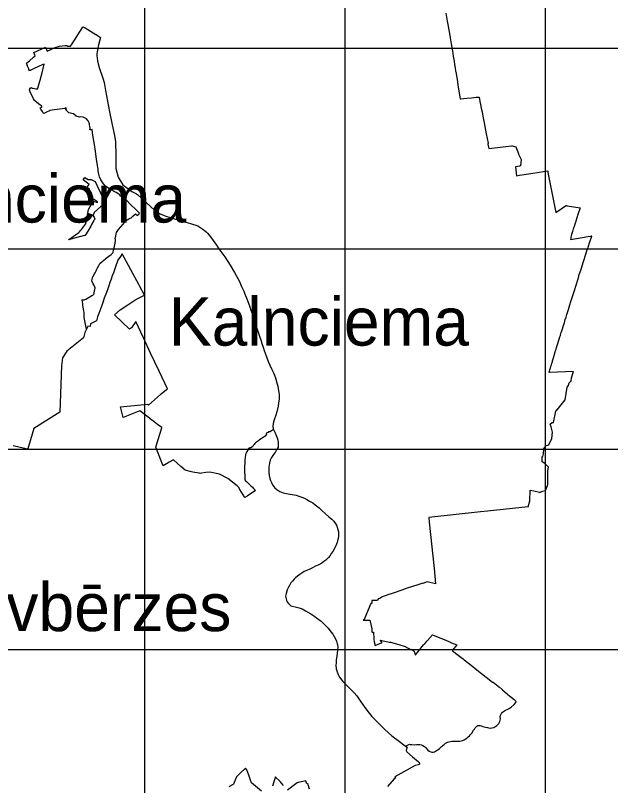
# Model space of a CAD drawing. Extents: x 459000 to 506121, y 222400 to 317452.
# Drawn here: x 471774 to 486631, y 281617 to 300827 of the extents above; entities that cross this region are included whole.
import ezdxf

# ---------------------------------------------------------------- set-up
doc = ezdxf.new("R2010")
doc.units = 0
for name, color, linetype in [('novada_robeza', 7, 'Continuous'), ('pagastu_nosaukumi', 7, 'Continuous'), ('pagastu_robezas', 7, 'Continuous'), ('Ramis', 7, 'Continuous')]:
    doc.layers.add(name, color=color, linetype=linetype)

msp = doc.modelspace()

# ---------------------------------------------------------------- linework, layer by layer
at = {"layer": 'novada_robeza'}
for points in [[(482522, 300886), (482555, 300684), (482570, 300597), (482585, 300509), (482601, 300416), (482616, 300323), (482625, 300269), (482634, 300216), (482651, 300121), (482667, 300027), (482669, 300019), (482671, 300011), (482677, 299976), (482684, 299940), (482704, 299814), (482725, 299688), (482737, 299605), (482749, 299523), (482763, 299434), (482765, 299417), (482797, 299228), (482828, 299039), (482873, 298743), (482887, 298744), (482891, 298745), (483040, 298762), (483162, 298775), (483275, 298787), (483353, 298791), (483370, 298681), (483384, 298609), (483403, 298516), (483423, 298424), (483443, 298317), (483475, 298146), (483527, 297876), (483572, 297638), (483570, 297614), (483588, 297508), (483953, 297551), (484012, 297560), (484161, 297576), (484171, 297574), (484267, 297551), (484334, 297383), (484327, 297382), (484399, 297232), (484395, 297223), (484384, 297074), (484354, 297069), (484256, 297051), (484286, 296823), (484361, 296841), (484638, 296886), (484846, 296918), (485060, 296948), (485066, 296912), (485260, 295909), (485530, 296098), (485541, 296079), (485717, 296053), (485870, 296031), (485817, 295865), (485764, 295698), (485762, 295690), (485759, 295683), (485739, 295624), (485720, 295565), (485714, 295548), (485708, 295532), (485703, 295516), (485699, 295500), (485688, 295467), (485677, 295435), (485658, 295364), (485638, 295294), (485635, 295267), (485632, 295239), (485777, 295263), (485921, 295287), (485967, 295294), (486012, 295302), (486065, 295310), (486117, 295318), (486138, 295322), (486159, 295326)], [(484571, 288568), (484571, 288572), (484614, 288720), (484620, 288986), (484716, 288971), (484852, 288933), (484861, 288930), (484862, 288930), (484930, 288957), (485006, 288979), (485057, 289098), (485060, 289123), (485066, 289343), (485068, 289447), (485065, 289469), (485079, 289558), (485070, 289568), (485067, 289571), (485058, 289580), (484999, 289645), (484936, 289684), (484924, 289690), (484925, 289825), (484942, 289822), (484952, 289892), (484964, 290017), (485023, 290101), (485092, 290119), (485168, 290270), (485181, 290430), (485146, 290567), (485123, 290634), (485175, 290677), (485182, 290677), (485199, 290671), (485205, 290674), (485267, 290958), (485271, 290961), (485285, 290990), (485296, 290991), (485496, 291242), (485544, 291554), (485581, 291592), (485581, 291608), (485593, 291664), (485640, 291702), (485646, 291705), (485656, 291786), (485702, 291942), (485703, 291946), (485102, 291920), (485094, 291921), (485099, 291938), (485104, 291955), (485112, 291983), (485120, 292010), (485127, 292029), (485133, 292048), (485137, 292062), (485141, 292076), (485152, 292113), (485163, 292150), (485171, 292172), (485178, 292194), (485181, 292203), (485183, 292213), (485207, 292290), (485230, 292367), (485232, 292376), (485233, 292384), (485235, 292390), (485237, 292397), (485240, 292402), (485242, 292407), (485241, 292408), (485239, 292408), (485242, 292416), (485245, 292424), (485258, 292465), (485270, 292505), (485284, 292547), (485297, 292590), (485314, 292644), (485332, 292698), (485348, 292753), (485365, 292807), (485372, 292826), (485378, 292845), (485384, 292864), (485390, 292882), (485401, 292919), (485412, 292956), (485431, 293013), (485449, 293070), (485463, 293114), (485476, 293158), (485500, 293239), (485520, 293304), (485540, 293369), (485577, 293489), (485614, 293609), (485639, 293688), (485664, 293767), (485687, 293840), (485710, 293912), (485727, 293967), (485769, 294101), (485811, 294235), (485836, 294317), (485839, 294327), (485842, 294337), (485895, 294501), (485954, 294686), (486014, 294871), (486032, 294929), (486050, 294987), (486051, 294990), (486051, 294992), (486106, 295155), (486160, 295318), (486158, 295318), (486157, 295319), (486158, 295322), (486159, 295326)], [(484571, 288568), (483555, 288459), (483386, 288441), (482092, 288302), (482104, 288190), (482227, 287030), (482264, 286652), (482264, 286649), (482052, 286698), (481943, 286661), (481941, 286662), (481820, 286624), (481556, 286537), (481424, 286492), (481203, 286418), (481067, 286373), (481004, 286352), (481005, 286346), (480932, 286321), (480887, 286289), (480837, 286277), (480832, 286279), (480814, 286234), (480671, 286233), (480675, 286164), (480648, 286162), (480624, 286103), (480480, 285762), (480457, 285742), (480466, 285742), (480496, 285742), (480526, 285743), (480564, 285743), (480566, 285743), (480620, 285743), (480667, 285529), (480669, 285507), (480672, 285481), (480674, 285455), (480676, 285440), (480687, 285440), (480714, 285442), (480722, 285278), (480723, 285268), (480731, 285204), (480757, 285114), (480926, 285187), (480875, 285244), (480917, 285238), (481104, 285197), (481145, 285194), (481192, 285181), (481345, 285134), (481507, 285082), (481561, 285053), (481705, 284988), (481715, 284982), (481724, 284973), (481741, 284899), (481754, 284873), (481760, 284876), (481768, 284886), (481836, 284971), (481960, 285125), (481987, 285155), (481991, 285151), (482046, 285218), (482057, 285232), (482182, 285379), (482408, 285286), (482519, 285240), (482608, 285203), (482661, 285180), (482793, 285126), (482792, 285125), (482685, 284994), (482685, 284980), (482687, 284979), (482826, 284871), (482891, 284820), (482949, 284775), (482976, 284754), (483194, 284586), (483254, 284538), (483683, 284194), (483696, 284198), (483825, 284095), (483834, 284077), (483848, 284077), (483928, 284014), (483932, 284004), (484001, 283951), (483993, 283947), (484030, 283918), (484049, 283903), (484053, 283900), (484098, 283866), (484151, 283823), (484220, 283763), (484260, 283728), (484266, 283723), (484275, 283712)], [(483420, 283101), (483442, 283093), (483505, 283072), (483559, 283063), (483584, 283059), (483634, 283053), (483665, 283054), (483720, 283066), (483744, 283081), (483769, 283095), (483791, 283113), (483814, 283137), (483838, 283163), (483858, 283198), (483865, 283216), (483879, 283283), (483878, 283344), (483884, 283366), (483889, 283385), (483906, 283413), (483930, 283445), (483955, 283465), (484009, 283496), (484048, 283516), (484083, 283533), (484106, 283548), (484145, 283577), (484220, 283637), (484262, 283690), (484275, 283712)], [(481511, 282597), (481614, 282646), (481629, 282644), (481667, 282640), (481724, 282637), (481783, 282642), (481827, 282645), (481872, 282639), (481908, 282631), (481945, 282614), (481982, 282591), (482011, 282564), (482067, 282503), (482102, 282477), (482141, 282459), (482171, 282453), (482204, 282454), (482235, 282461), (482263, 282472), (482288, 282488), (482315, 282507), (482353, 282533), (482380, 282560), (482403, 282580), (482428, 282602), (482448, 282621), (482477, 282645), (482511, 282676), (482559, 282703), (482590, 282712), (482632, 282719), (482670, 282721), (482702, 282724), (482749, 282723), (482799, 282724), (482807, 282723), (482831, 282722), (482840, 282722), (482863, 282724), (482897, 282730), (482946, 282740), (482977, 282754), (483004, 282771), (483040, 282800), (483078, 282833), (483108, 282861), (483129, 282884), (483164, 282925), (483211, 282997), (483230, 283027), (483253, 283056), (483271, 283077), (483294, 283098), (483317, 283113), (483345, 283116), (483375, 283113), (483409, 283105), (483420, 283101)], [(481511, 282597), (481551, 282578), (481547, 282552), (481540, 282530), (481534, 282515), (481531, 282506), (481528, 282496), (481529, 282488), (481535, 282475), (481544, 282461), (481688, 282338), (481828, 282217), (481851, 282192), (481856, 282186), (481859, 282177), (481860, 282156), (481860, 282155), (481827, 282131), (481750, 282122), (481469, 281962), (481247, 281835), (481274, 281814), (481231, 281787), (481066, 281595)], [(477920, 281477), (477666, 281688), (477654, 281731), (477603, 281875), (477553, 282012), (477514, 282049), (477490, 282026), (477410, 281949), (477294, 281838), (477249, 281733), (477215, 281652), (477211, 281644), (477102, 281583)], [(478465, 281616), (478382, 281715), (478364, 281734), (478355, 281743), (478276, 281822), (478263, 281835), (478224, 281714), (478188, 281600)], [(479116, 281531), (479085, 281637), (479081, 281645), (479042, 281679), (479024, 281736), (478844, 281698), (478822, 281693), (478805, 281685), (478771, 281660), (478564, 281501)]]:
    msp.add_lwpolyline(points, dxfattribs=at)
at = {"layer": 'pagastu_robezas'}
for points in [[(473547, 292998), (473495, 293293), (473494, 293330), (473491, 293410), (473490, 293419), (473486, 293446), (473477, 293510), (473461, 293592), (473455, 293647), (473448, 293683), (473441, 293739), (473464, 293731), (473492, 293733), (473507, 293741), (473529, 293752), (473613, 293797), (473686, 293839), (473709, 293851), (473724, 293869), (473729, 293875), (473735, 293883), (473738, 293887), (473742, 293907), (473756, 293990), (473762, 294028), (473739, 294087), (473719, 294128), (473718, 294130), (473680, 294204), (473687, 294242), (473702, 294290), (473711, 294308), (473751, 294381), (473764, 294409), (473789, 294455), (473800, 294477), (473811, 294500), (473826, 294531), (473858, 294590), (473865, 294606), (473880, 294637), (473929, 294682), (473930, 294683), (473938, 294689), (474024, 294757), (474041, 294771), (474109, 294821), (474161, 294865), (474162, 294865), (474190, 294887), (474203, 294902), (474211, 294919), (474223, 294968), (474229, 294996), (474262, 295143), (474263, 295149), (474272, 295205), (474273, 295211), (474272, 295240), (474272, 295240), (474262, 295259), (474274, 295298), (474284, 295324), (474293, 295383), (474299, 295415), (474314, 295441), (474352, 295491), (474463, 295617), (474493, 295654), (474556, 295722), (474563, 295725), (474605, 295751), (474639, 295769), (474665, 295776), (474707, 295818), (474770, 295880), (474813, 295833), (474860, 295879), (474863, 295882), (474876, 295895), (474876, 295895), (474757, 296011), (474673, 296089), (474522, 296240), (474476, 296273), (474382, 296325), (474385, 296329), (474393, 296345), (474370, 296357), (474355, 296367), (474355, 296367), (474355, 296368), (474287, 296408), (474146, 296485), (474081, 296530), (474027, 296572), (473976, 296623), (473939, 296677), (473908, 296729), (473877, 296803), (473859, 296865), (473851, 296908), (473844, 296952), (473837, 296991), (473830, 297037), (473824, 297087), (473800, 297243), (473793, 297302), (473775, 297437), (473745, 297608), (473707, 297839), (473697, 297904), (473688, 297980), (473661, 297976), (473640, 297974), (473636, 297974), (473641, 298012), (473634, 298057), (473627, 298102), (473624, 298119), (473617, 298150), (473594, 298196), (473547, 298244), (473498, 298276), (473462, 298289), (473409, 298297), (473376, 298287), (473293, 298314), (473223, 298371), (473110, 298395), (473029, 298478), (473050, 298499), (473032, 298521), (473012, 298505), (472627, 298457), (472625, 298448), (472550, 298412), (472481, 298378), (472477, 298377), (472447, 298430), (472410, 298491), (472400, 298505), (472388, 298519), (472392, 298521), (472441, 298546), (472423, 298570), (472403, 298587), (472363, 298617), (472293, 298670), (472255, 298705), (472225, 298749), (472133, 298938), (472131, 298958), (472121, 298971), (472124, 298977), (472160, 299030), (472190, 299016), (472219, 299010), (472249, 299002), (472253, 299002), (472283, 298996), (472290, 298996), (472311, 298995), (472335, 298998), (472337, 298998), (472333, 299009), (472384, 299185), (472392, 299214), (472430, 299333), (472441, 299398), (472494, 299607), (472459, 299601), (472350, 299556), (472226, 299497), (472142, 299456), (472129, 299451), (472112, 299481), (472107, 299493), (472100, 299512), (472092, 299531), (472086, 299545), (472080, 299561), (472056, 299621), (472051, 299635), (472096, 299673), (472125, 299698), (472230, 299785), (472265, 299816), (472238, 299898), (472526, 300038), (472569, 299937), (472770, 300027), (472875, 300058), (473010, 300075), (473056, 300073), (473085, 300061), (473151, 300061), (473171, 300094), (473246, 300213), (473387, 300431), (473396, 300445), (473461, 300545), (473512, 300515), (473783, 300354), (473791, 300350), (473796, 300347), (473800, 300345), (473899, 300279), (473850, 300089), (473813, 299921), (473806, 299869), (473804, 299824), (473824, 299692), (473841, 299622), (473866, 299531), (473968, 299236), (473990, 299151), (474020, 298955), (474122, 298424), (474191, 298099), (474247, 297833), (474271, 297675), (474278, 297333), (474282, 297050), (474283, 297012), (474336, 296796), (474460, 296604), (474460, 296603), (474578, 296508), (474677, 296437), (474801, 296378), (474824, 296362), (475248, 295971), (475391, 295878), (475526, 295818), (475639, 295783), (475858, 295724), (476149, 295635), (476324, 295580), (476357, 295566), (476451, 295497), (476534, 295429), (476567, 295399), (476620, 295334), (476713, 295215), (476790, 295098), (476855, 295001), (476998, 294802), (477138, 294594), (477244, 294417), (477367, 294189), (477422, 294063), (477473, 293952), (477493, 293902), (477552, 293756), (477625, 293561), (477655, 293474), (477685, 293388), (477706, 293322), (477727, 293255), (477778, 293104), (477803, 293030), (477835, 292928), (477866, 292827), (477897, 292734), (477927, 292641), (477956, 292554), (477985, 292467), (478007, 292401), (478030, 292335), (478081, 292197), (478122, 292106), (478177, 291997), (478225, 291893), (478270, 291785), (478311, 291630), (478325, 291576), (478350, 291416), (478355, 291379), (478358, 291350), (478358, 291329), (478355, 291264), (478344, 291159), (478333, 291083), (478304, 290943), (478275, 290856), (478230, 290741), (478208, 290649), (478200, 290572), (478209, 290516), (478217, 290499)], [(474041, 296262), (474038, 296258), (473951, 296101), (473936, 296080), (473903, 296057), (473743, 295913), (473717, 295839), (473708, 295842), (473710, 295836), (473742, 295791), (473759, 295757), (473756, 295748), (473744, 295726), (473733, 295708), (473678, 295612), (473657, 295571), (473585, 295449), (473528, 295356), (473514, 295332), (473514, 295332), (473499, 295336), (473405, 295311), (473398, 295309), (473097, 295228), (473109, 295238), (473357, 295410), (473377, 295429), (473395, 295452), (473422, 295484), (473523, 295616), (473559, 295743), (473601, 295985), (473712, 296193), (473823, 296159), (473825, 296159), (473824, 296179), (473690, 296257), (473649, 296278), (473646, 296280), (473627, 296503), (473561, 296534), (473569, 296546), (473617, 296613), (473464, 296723), (473507, 296787), (473588, 296733), (473664, 296737), (473762, 296683), (473816, 296579), (473831, 296535), (473870, 296457), (473927, 296343), (473950, 296305), (473962, 296290), (473971, 296285), (474023, 296264), (474055, 296324), (474115, 296438), (474116, 296440), (474126, 296469), (474148, 296455), (474041, 296262)], [(478217, 290499), (478146, 290449), (478136, 290442), (478129, 290437), (478121, 290443), (478108, 290444), (478096, 290438), (478084, 290427), (478071, 290412), (478064, 290431), (478033, 290398), (478046, 290382), (478007, 290336), (477956, 290302), (477893, 290255), (477860, 290231), (477844, 290220), (477815, 290198), (477804, 290189), (477790, 290180), (477771, 290162), (477754, 290147), (477735, 290126), (477713, 290097), (477700, 290078), (477672, 290055), (477666, 290050), (477645, 290034), (477639, 290041), (477637, 290040), (477627, 290038), (477620, 290036), (477607, 290030), (477593, 290022), (477582, 290000), (477581, 289999), (477545, 289937), (477525, 289900), (477517, 289866), (477508, 289801), (477500, 289737), (477505, 289736), (477505, 289733), (477500, 289669), (477499, 289647), (477493, 289590), (477493, 289567), (477492, 289519), (477496, 289439), (477497, 289399), (477499, 289386), (477499, 289361), (477500, 289336), (477501, 289293), (477503, 289241), (477503, 289241), (477521, 289220), (477544, 289199), (477643, 289103), (477661, 289085), (477681, 289066), (477719, 289028), (477753, 288997), (477770, 288981), (477758, 288972), (477568, 288846), (477558, 288839), (477501, 288802), (477501, 288801), (477373, 289001), (477367, 289014), (477367, 289020), (477369, 289025), (477372, 289028), (477363, 289038), (477356, 289045), (477353, 289049), (477313, 289094), (477075, 289276), (476870, 289385), (476630, 289432), (476627, 289432), (476525, 289422), (476417, 289410), (476389, 289405), (476365, 289407), (476205, 289438), (476140, 289451), (476008, 289483), (475907, 289573), (475724, 289746), (475611, 289682), (475561, 289650), (475550, 289643), (475461, 289593), (475456, 289607), (475281, 290059), (475341, 290252), (475430, 290538), (475432, 290545), (475325, 290626), (475198, 290723), (475182, 290735), (475129, 290775), (475118, 290783), (475086, 290808), (474881, 290967), (474468, 290799), (474401, 291068), (474825, 291103), (475077, 291127), (475099, 291108), (475397, 291374), (475415, 291390), (475550, 291497), (475569, 291512), (475361, 291954), (475148, 292404), (474968, 292784), (474778, 293191), (474672, 293032), (474626, 293004), (474244, 293359), (474386, 293481), (474581, 293611), (474780, 293739), (474995, 293851), (474870, 294086), (474855, 294114), (474707, 294390), (474443, 294880), (474399, 294817), (474335, 294721), (474282, 294579), (474248, 294484), (474219, 294406), (474193, 294328), (474164, 294252), (474134, 294165), (474106, 294085), (474079, 294011), (474045, 293917), (473993, 293771), (473955, 293665), (473930, 293593), (473909, 293528), (473880, 293455), (473856, 293392), (473827, 293307), (473795, 293209), (473646, 293131), (473644, 293069), (473581, 293075), (473579, 293070), (473549, 292998), (473547, 292998)], [(473547, 292998), (473506, 292921), (473475, 292782), (473055, 292456), (472948, 292286), (472929, 292089), (472884, 290930), (472238, 290525), (472089, 290015), (472090, 290010), (472085, 290010), (471896, 290051), (471715, 290090)], [(478217, 290499), (478256, 290415), (478284, 290351), (478307, 290291), (478323, 290229), (478336, 290171), (478337, 290114), (478331, 290057), (478294, 289990), (478266, 289941), (478215, 289878), (478165, 289800), (478137, 289730), (478117, 289658), (478104, 289563), (478104, 289490), (478103, 289428), (478111, 289349), (478127, 289273), (478142, 289225), (478165, 289176), (478193, 289121), (478245, 289050), (478299, 289002), (478371, 288951), (478461, 288918), (478585, 288892), (478779, 288857), (478852, 288834), (478926, 288807), (478994, 288782), (479050, 288752), (479114, 288715), (479197, 288669), (479258, 288622), (479353, 288542), (479427, 288475), (479517, 288397), (479595, 288324), (479676, 288258), (479722, 288211), (479760, 288162), (479788, 288112), (479810, 288061), (479825, 288003), (479839, 287950), (479840, 287895), (479839, 287835), (479831, 287782), (479817, 287724), (479803, 287676), (479787, 287635), (479733, 287512), (479696, 287457), (479660, 287402), (479629, 287353), (479587, 287310), (479520, 287241), (479469, 287203), (479421, 287162), (479350, 287121), (479268, 287092), (479171, 287041), (479106, 287008), (478979, 286957), (478920, 286918), (478871, 286883), (478816, 286843), (478769, 286800), (478732, 286765), (478695, 286718), (478650, 286670), (478614, 286608), (478582, 286553), (478556, 286499), (478533, 286405), (478519, 286345), (478529, 286276), (478551, 286208), (478588, 286155), (478649, 286104), (478789, 286070), (478858, 286050), (478929, 286023), (479017, 285976), (479152, 285902), (479250, 285832), (479289, 285798), (479403, 285717), (479471, 285651), (479539, 285584), (479579, 285543), (479650, 285454), (479696, 285395), (479728, 285338), (479765, 285280), (479789, 285220), (479805, 285156), (479813, 285126), (479820, 285075), (479815, 284995), (479795, 284849), (479785, 284757), (479777, 284671), (479773, 284617), (479781, 284527), (479802, 284457), (479829, 284384), (479868, 284317), (479947, 284214), (480059, 284102), (480158, 284007), (480232, 283932), (480294, 283857), (480400, 283707), (480522, 283534), (480603, 283427), (480673, 283341), (480779, 283233), (480998, 283019), (481171, 282860), (481358, 282717), (481470, 282631), (481511, 282597)]]:
    msp.add_lwpolyline(points, dxfattribs=at)
at = {"layer": 'Ramis'}
for p, q in [((475000, 310000), (475000, 240000)), ((480000, 310000), (480000, 240000)), ((485000, 310000), (485000, 240000)), ((505000, 300000), (460000, 300000)), ((505000, 295000), (460000, 295000)), ((505000, 290000), (460000, 290000)), ((505000, 285000), (460000, 285000))]:
    msp.add_line(p, q, dxfattribs=at)

# ---------------------------------------------------------------- texts
at = {"layer": 'pagastu_nosaukumi'}
for s, p in [('Kalnciema', (468545, 295661)), ('Kalnciema', (475604, 292591)), ('Līvbērzes', (470209, 285469))]:
    msp.add_text(s, height=1200, dxfattribs=at).set_placement(p)

doc.saveas('drawing.dxf')
